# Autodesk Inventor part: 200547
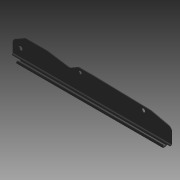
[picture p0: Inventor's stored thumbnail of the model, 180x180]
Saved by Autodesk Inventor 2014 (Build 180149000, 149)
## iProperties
Created: 2007-10
Part Number: 200547
Document SubType Name: Modeling
Designer: TH
Density: 7.85 g/cm^3
Mass: 510.334 g
Surface Area: 671.811 cm^2
Volume: 65.0106 cm^3
Material: Steel
Description: RAIL SIDE - LEFT OUTER
Appearance: Dark Gray
Component Category: Lower Component
Author: TH
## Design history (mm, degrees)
node "200050" dims "d1" = 10
body "Solid1"
tag "TaggingFeature3"
feature "DerivedBody::D-200050" dims "d1" = 10
